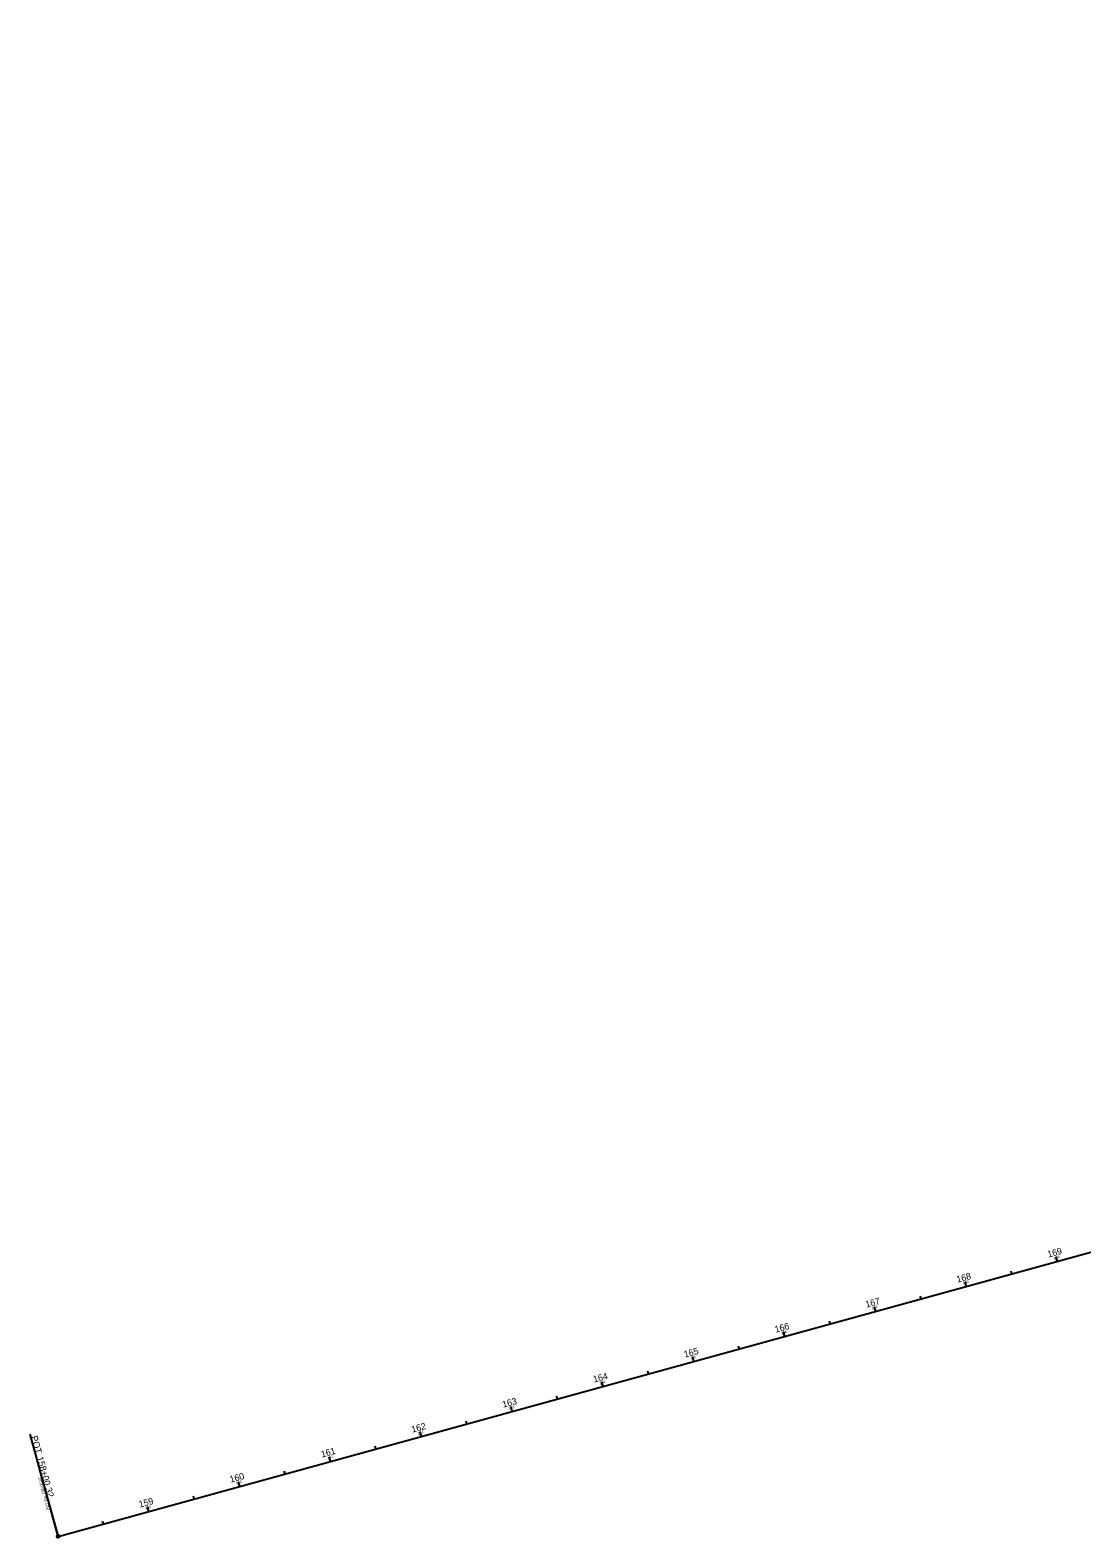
# Model space of a CAD drawing. Extents: x 2129507 to 2138391, y 657622 to 659877.
# Drawn here: x 2129507 to 2130623, y 657716 to 659316 of the extents above; entities that cross this region are included whole.
import ezdxf

# ---------------------------------------------------------------- set-up
doc = ezdxf.new("R2010")
doc.units = 0
for name, color, linetype in [('Default', 7, 'Continuous'), ('GE_X_Alignment_1000_Stations', 7, 'Continuous'), ('GE_X_Alignment_100_Stations', 7, 'Continuous'), ('GE_X_Alignment_500_Stations', 7, 'Continuous'), ('GE_X_CL_20', 7, 'Continuous'), ('MT_P_CL_20', 7, 'Continuous')]:
    doc.layers.add(name, color=color, linetype=linetype)

msp = doc.modelspace()

# ---------------------------------------------------------------- linework, layer by layer
at = {"layer": 'Default'}
for centre in [(2130597.2, 658009.1), (2130500.8, 657982.5), (2130404.4, 657956), (2130307.9, 657929.5), (2130211.5, 657902.9), (2130211.5, 657902.9), (2130115.1, 657876.4), (2130018.7, 657849.9), (2129922.3, 657823.3), (2129825.9, 657796.8), (2129729.5, 657770.2), (2129729.5, 657770.2), (2129729.5, 657770.2), (2129633, 657743.7), (2129536.9, 657717.3), (2129536.9, 657717.3), (2129536.9, 657717.3)]:
    msp.add_circle(centre, 0.0000833, dxfattribs=at)
at = {"layer": 'GE_X_Alignment_1000_Stations'}
for p, q in [((2130211.5, 657902.9), (2130210.7, 657905.8)), ((2129536.9, 657717.3), (2129507.1, 657825.7)), ((2129729.5, 657770.2), (2129728.1, 657775.1))]:
    msp.add_line(p, q, dxfattribs=at)
msp.add_circle((2129536.9, 657717.3), 1.5, dxfattribs=at)
at = {"layer": 'GE_X_Alignment_100_Stations'}
for p, q in [((2130597.2, 658009.1), (2130595.9, 658013.9)), ((2130549, 657995.8), (2130548.2, 657998.7)), ((2130500.8, 657982.5), (2130499.4, 657987.4)), ((2130452.6, 657969.3), (2130451.8, 657972.2)), ((2130404.4, 657956), (2130403, 657960.8)), ((2130307.9, 657929.5), (2130306.6, 657934.3)), ((2130356.1, 657942.7), (2130355.4, 657945.6)), ((2130259.7, 657916.2), (2130258.9, 657919.1)), ((2130211.5, 657902.9), (2130210.2, 657907.7)), ((2130163.3, 657889.7), (2130162.5, 657892.6)), ((2130115.1, 657876.4), (2130113.8, 657881.2)), ((2130018.7, 657849.9), (2130017.4, 657854.7)), ((2130066.9, 657863.1), (2130066.1, 657866)), ((2129970.5, 657836.6), (2129969.7, 657839.5)), ((2129536.9, 657717.3), (2129507.1, 657825.7)), ((2129922.3, 657823.3), (2129921, 657828.1)), ((2129874.1, 657810.1), (2129873.3, 657812.9)), ((2129825.9, 657796.8), (2129824.5, 657801.6)), ((2129729.5, 657770.2), (2129728.1, 657775.1)), ((2129777.7, 657783.5), (2129776.9, 657786.4)), ((2129681.2, 657757), (2129680.4, 657759.9)), ((2129633, 657743.7), (2129631.7, 657748.5)), ((2129584.8, 657730.4), (2129584, 657733.3))]:
    msp.add_line(p, q, dxfattribs=at)
msp.add_circle((2129536.9, 657717.3), 1.5, dxfattribs=at)
at = {"layer": 'GE_X_Alignment_500_Stations'}
for p, q in [((2130597.2, 658009.1), (2130596.4, 658012)), ((2130500.8, 657982.5), (2130500, 657985.4)), ((2130404.4, 657956), (2130403.6, 657958.9)), ((2130307.9, 657929.5), (2130307.1, 657932.4)), ((2130211.5, 657902.9), (2130210.2, 657907.7)), ((2130115.1, 657876.4), (2130114.3, 657879.3)), ((2130018.7, 657849.9), (2130017.9, 657852.7)), ((2129536.9, 657717.3), (2129507.1, 657825.7)), ((2129922.3, 657823.3), (2129921.5, 657826.2)), ((2129825.9, 657796.8), (2129825.1, 657799.7)), ((2129729.5, 657770.2), (2129728.1, 657775.1)), ((2129633, 657743.7), (2129632.2, 657746.6))]:
    msp.add_line(p, q, dxfattribs=at)
msp.add_circle((2129536.9, 657717.3), 1.5, dxfattribs=at)
at = {"layer": 'GE_X_CL_20'}
for p, q in [((2129536.9, 657717.3), (2135344.6, 659315.7)), ((2130597.2, 658009.1), (2130596.7, 658011)), ((2130549, 657995.8), (2130548.4, 657997.7)), ((2130500.8, 657982.5), (2130500.2, 657984.5)), ((2130452.6, 657969.3), (2130452, 657971.2)), ((2130404.4, 657956), (2130403.8, 657957.9)), ((2130307.9, 657929.5), (2130307.4, 657931.4)), ((2130356.1, 657942.7), (2130355.6, 657944.7)), ((2130259.7, 657916.2), (2130259.2, 657918.1)), ((2130211.5, 657902.9), (2130211, 657904.9)), ((2130163.3, 657889.7), (2130162.8, 657891.6)), ((2130115.1, 657876.4), (2130114.6, 657878.3)), ((2130018.7, 657849.9), (2130018.2, 657851.8)), ((2130066.9, 657863.1), (2130066.4, 657865.1)), ((2129970.5, 657836.6), (2129970, 657838.5)), ((2129922.3, 657823.3), (2129921.7, 657825.2)), ((2129874.1, 657810.1), (2129873.5, 657812)), ((2129536.7, 657718.2), (2129517.5, 657787.8)), ((2129825.9, 657796.8), (2129825.3, 657798.7)), ((2129729.5, 657770.2), (2129728.9, 657772.2)), ((2129777.7, 657783.5), (2129777.1, 657785.4)), ((2129681.2, 657757), (2129680.7, 657758.9)), ((2129633, 657743.7), (2129632.5, 657745.6)), ((2129584.8, 657730.4), (2129584.3, 657732.4))]:
    msp.add_line(p, q, dxfattribs=at)
msp.add_circle((2129536.9, 657717.3), 1, dxfattribs=at)
at = {"layer": 'MT_P_CL_20'}
msp.add_line((2129536.9, 657717.3), (2135344.6, 659315.7), dxfattribs=at)

# ---------------------------------------------------------------- texts
at = {"layer": 'GE_X_Alignment_1000_Stations'}
for s, rotation, p in [('POT', 285.3886, (2129507.9, 657823)), ('158+00.32', 285.3886, (2129514, 657801)), ('160', 15.3886, (2129719.9, 657774.2))]:
    msp.add_text(s, height=7, rotation=rotation, dxfattribs=at).set_placement(p)
at = {"layer": 'GE_X_Alignment_100_Stations'}
for s, rotation, p in [('169', 15.3886, (2130587.7, 658013.1)), ('168', 15.3886, (2130491.2, 657986.5)), ('167', 15.3886, (2130394.6, 657959.9)), ('166', 15.3886, (2130298.3, 657933.4)), ('165', 15.3886, (2130201.9, 657906.9)), ('164', 15.3886, (2130105.6, 657880.4)), ('163', 15.3886, (2130009.1, 657853.8)), ('162', 15.3886, (2129912.7, 657827.3)), ('POT', 285.3886, (2129507.9, 657823)), ('161', 15.3886, (2129816.7, 657800.9)), ('158+00.32', 285.3886, (2129514, 657801)), ('160', 15.3886, (2129719.9, 657774.2)), ('159', 15.3886, (2129623.5, 657747.7))]:
    msp.add_text(s, height=7, rotation=rotation, dxfattribs=at).set_placement(p)
at = {"layer": 'GE_X_Alignment_500_Stations'}
for s, rotation, p in [('165', 15.3886, (2130201.9, 657906.9)), ('POT', 285.3886, (2129507.9, 657823)), ('158+00.32', 285.3886, (2129514, 657801)), ('160', 15.3886, (2129719.9, 657774.2))]:
    msp.add_text(s, height=7, rotation=rotation, dxfattribs=at).set_placement(p)
at = {"layer": 'GE_X_CL_20'}
for s, rotation, p in [('169', 15.3886, (2130593.5, 658011.2)), ('168', 15.3886, (2130497.2, 657984.7)), ('167', 15.3886, (2130400.6, 657958.1)), ('166', 15.3886, (2130304.3, 657931.6)), ('165', 15.3886, (2130207.9, 657905)), ('164', 15.3886, (2130111.5, 657878.5)), ('163', 15.3886, (2130015, 657852)), ('162', 15.3886, (2129918.6, 657825.4)), ('161', 15.3886, (2129822.7, 657799)), ('POT Sta. 158+00.32', 105.3886, (2129527.6, 657745.8)), ('160', 15.3886, (2129725.8, 657772.3)), ('159', 15.3886, (2129629.4, 657745.8))]:
    msp.add_text(s, height=2.8, rotation=rotation, dxfattribs=at).set_placement(p)

doc.saveas('drawing.dxf')
